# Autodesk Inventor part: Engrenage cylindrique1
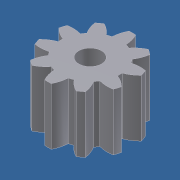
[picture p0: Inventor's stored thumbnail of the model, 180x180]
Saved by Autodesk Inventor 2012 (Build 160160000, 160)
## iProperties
Created: 2011-10
Part Number: Engrenage cylindrique1
Material: Acier
Document SubType Name: Modeling
Designer: Laur
Density: 1 g/cm^3
CustomPartVersion: 1
Author: Laur
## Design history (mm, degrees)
sketch "Sketch1"
  geometry: C1 r 1.74 at (0, 0)
  constraints: 1 centre point
  dimensions: "d0" = 3.48 diameter of C1 (= da_da)
extrude "Extrusion1" new body sketch "Sketch1" distance "d1" = 2.6 (= da_b); taper "d2" = 0 deg
workplane "Work Plane2"
sketch "Sketch2"
  geometry: C1 r 1.74 at (0, 0) reference; C2 r 1.5 at (0, 0)
  constraints: 1 centre point, 1 coincident
  dimensions: "d3" = 3 diameter of C2 (= da_dw)
extrude_surface "ExtrusionSrf1" sketch "Sketch2" dims "d4" = 10, "d5" = 0
workplane "Work Plane8"
workplane "Work Plane9"
feature "Engrenage cylindrique" dims "da_b" = 2.6, "da_d" = 3, "da_aw" = 7.95, "da_da" = 3.48, "da_df" = 2.34, "da_dw" = 3, angle "da_beta" = 0 deg, "da_lefttooth" = 0, "da_righttooth" = 0
sketch "Esquisse3"
  geometry: C1 r 0.5 at (0, 0) reference
extrude "Extrusion2" cut sketch "Esquisse3" stored distance "d49" = 10; taper "d50" = 0 deg
node "Solide1"
node "Corps solides"
node "Corps surfaciques"
body "Srf1"
node "Référence1"
other parameters: "d16" = 7.95 (= da_aw), "d17" = 0, "d34" = 18 deg (computed from da_z), "d39" = 0, "d41" = 0, "d43" = 7.95 (= da_aw), "d46" = 7.95 (= da_aw), "d47" = 0, "d48" = 0
